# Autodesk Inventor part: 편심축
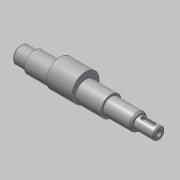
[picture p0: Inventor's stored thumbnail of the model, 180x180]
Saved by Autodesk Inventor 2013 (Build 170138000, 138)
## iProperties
Created: 2019-05
Part Number: 편심축
Material: 강철, 연강
Document SubType Name: Modeling
Designer: mduedu
Density: 1 g/cm^3
Author: mduedu
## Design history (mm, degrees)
sketch "스케치1"
  geometry: L1 (0, 0)-(14, 0); L2 (14, 0)-(14, 8.5); L3 (14, 8.5)-(0, 8.5); L4 (0, 8.5)-(0, 0); L5 (14, 0)-(92, 0); L6 (92, 0)-(92, 10.5); L7 (92, 10.5)-(14, 10.5); L8 (14, 10.5)-(14, 0); L9 (92, 8.5)-(92, 0); L10 (92, 0)-(121, 0); L11 (121, 0)-(121, 8.5); L12 (121, 8.5)-(92, 8.5); L13 (92, 8.5)-(92, 0); L14 (121, 0)-(141, 0); L15 (141, 0)-(141, 6); L16 (141, 6)-(121, 6); L17 (121, 6)-(121, 0)
  constraints: 34 end point, 8 parallel, 4 horizontal, 4 perpendicular
  dimensions: "d2" = 14 distance of L2.end L3.end; "d5" = 17 diameter of L3 L1; "d6" = 21 diameter of L7 L5; "d11" = 78 distance of L6.end L7.end (derived); "d12" = 141 distance between parallel lines of L15 L4; "d13" = 20 distance of L15.end L16.end; "d14" = 49 distance between parallel lines of L15 L6; "d15" = 12 diameter of L16 L14; "d16" = 17 diameter of L12 L10
revolve "회전1" sketch "스케치1" stored, may be unused: angle "d17" = 90 deg
node "작업 평면1"
sketch "스케치2"
  geometry: C1 r 14 at (0, 3.5); C2 r 10.5 at (0, 0) reference; 1 further point
  constraints: 1 centre point, 1 tangent, 1 vertical alignment
  dimensions: "d18" = 28 diameter of C1; "d21" = 3.5 distance of C1.centre point (0, 0) (derived)
extrude "돌출1" join sketch "스케치2" stored distance "d19" = 26; taper "d20" = 0 deg
hole "구멍2" diameter "d45" = 3.242; stored, may be unused: countersink angle "d49" = 60 deg, drill point angle "d51" = 118 deg; dims "d43" = 10, "d44" = 10, "d46" = 8, "d47" = 6.7, "d48" = 2, "d50" = 10
chamfer "모따기3" distance "d52" = 2; stored, may be unused: second distance "d53" = 2, angle "d54" = 30 deg
node "작업 평면2"
sketch "스케치3" dims "d32" = 14
  geometry: L1 (6, -2)-(-4, -2); L2 (-4, -2)-(-4, 2); L3 (-4, 2)-(6, 2); L4 (6, 2)-(6, -2); L5 (10, 8.5)-(10, -8.5) reference; 3 further points
  constraints: 8 end point, 2 midpoint, 2 parallel, 2 vertical alignment, 1 horizontal, 1 horizontal alignment, 1 perpendicular, 4 other
  dimensions: "d31" = 2 dimension on L5; "d33" = 4 distance between parallel lines of L3 L1
extrude "돌출2" cut sketch "스케치3" distance "d34" = 2.5; taper "d35" = 0 deg
chamfer "모따기1" distance "d36" = 1; stored, may be unused: second distance "d37" = 2, angle "d38" = 45 deg
fillet "모깎기1" dims "d39" = 0.3
chamfer "모따기2" distance "d40" = 1.82; stored, may be unused: second distance "d41" = 2, angle "d42" = 30 deg
fillet "모깎기2" dims "d55" = 2
fillet "모깎기3" dims "d56" = 0.5
node "솔리드1"
